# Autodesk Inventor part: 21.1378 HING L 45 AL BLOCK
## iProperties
Created: 2007-01
Part Number: 21.1378 HING L 45 AL BLOCK
Document SubType Name: Modeling
Designer: Andy Moles
Material: Aluminum-6061
Mass: 18.3886 g
Surface Area: 42.4477 cm^2
Volume: 6.78548 cm^3
Density: 2.71 g/cm^3
Author: Andy Moles
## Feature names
1. Extrusion1
2. Hole1
